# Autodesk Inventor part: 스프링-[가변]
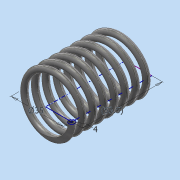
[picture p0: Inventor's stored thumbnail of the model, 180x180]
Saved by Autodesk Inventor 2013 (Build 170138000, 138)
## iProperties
Created: 2014-12
Part Number: 스프링-[가변]
Material: 강철, 탄소
Document SubType Name: Modeling
Designer: WINDOWS7
Mass: 80.0749 g
Surface Area: 103.229 cm^2
Volume: 10.1747 cm^3
Density: 7.87 g/cm^3
Author: WINDOWS7
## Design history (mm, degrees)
sketch "스케치1"
  geometry: L1 (0, 0)-(17.5, 0); L2 (17.5, 0)-(17.5, 48.5); L3 (17.5, 48.5)-(0, 48.5); L4 (0, 48.5)-(0, 0); C1 r 2 at (17.5, 0)
  constraints: 8 end point, 2 parallel, 1 centre point, 1 coincident, 1 horizontal, 1 perpendicular
  dimensions: "d0" = 35 diameter of L2 L4; "d2" = 48.5 distance of L1.end L2.end (derived); "d3" = 4 diameter of C1
feature "코일1" sketch "스케치1" pitch "d4" = 10; turns "d6" = 7.5; dims "d5" = 48.5 (= d2), "d7" = 0, angle "d8" = 90 deg, angle "d9" = 90 deg, "d10" = 0, "d11" = 0
sketch "스케치2"
  geometry: L1 (-19.5, 0)-(-15.5, 0) reference; 1 further point
  constraints: 1 horizontal alignment
extrude "돌출1" cut sketch "스케치2" distance "d12" = 10; taper "d13" = 0 deg
node "작업 평면1"
sketch "스케치3"
  geometry: L1 (-4, 0)-(0, 0) reference; 1 further point
  constraints: 1 horizontal alignment
extrude "돌출2" cut sketch "스케치3" distance "d14" = 10; taper "d15" = 0 deg
node "솔리드1"
node "절단 모서리 투영1"
node "절단 모서리 투영2"
